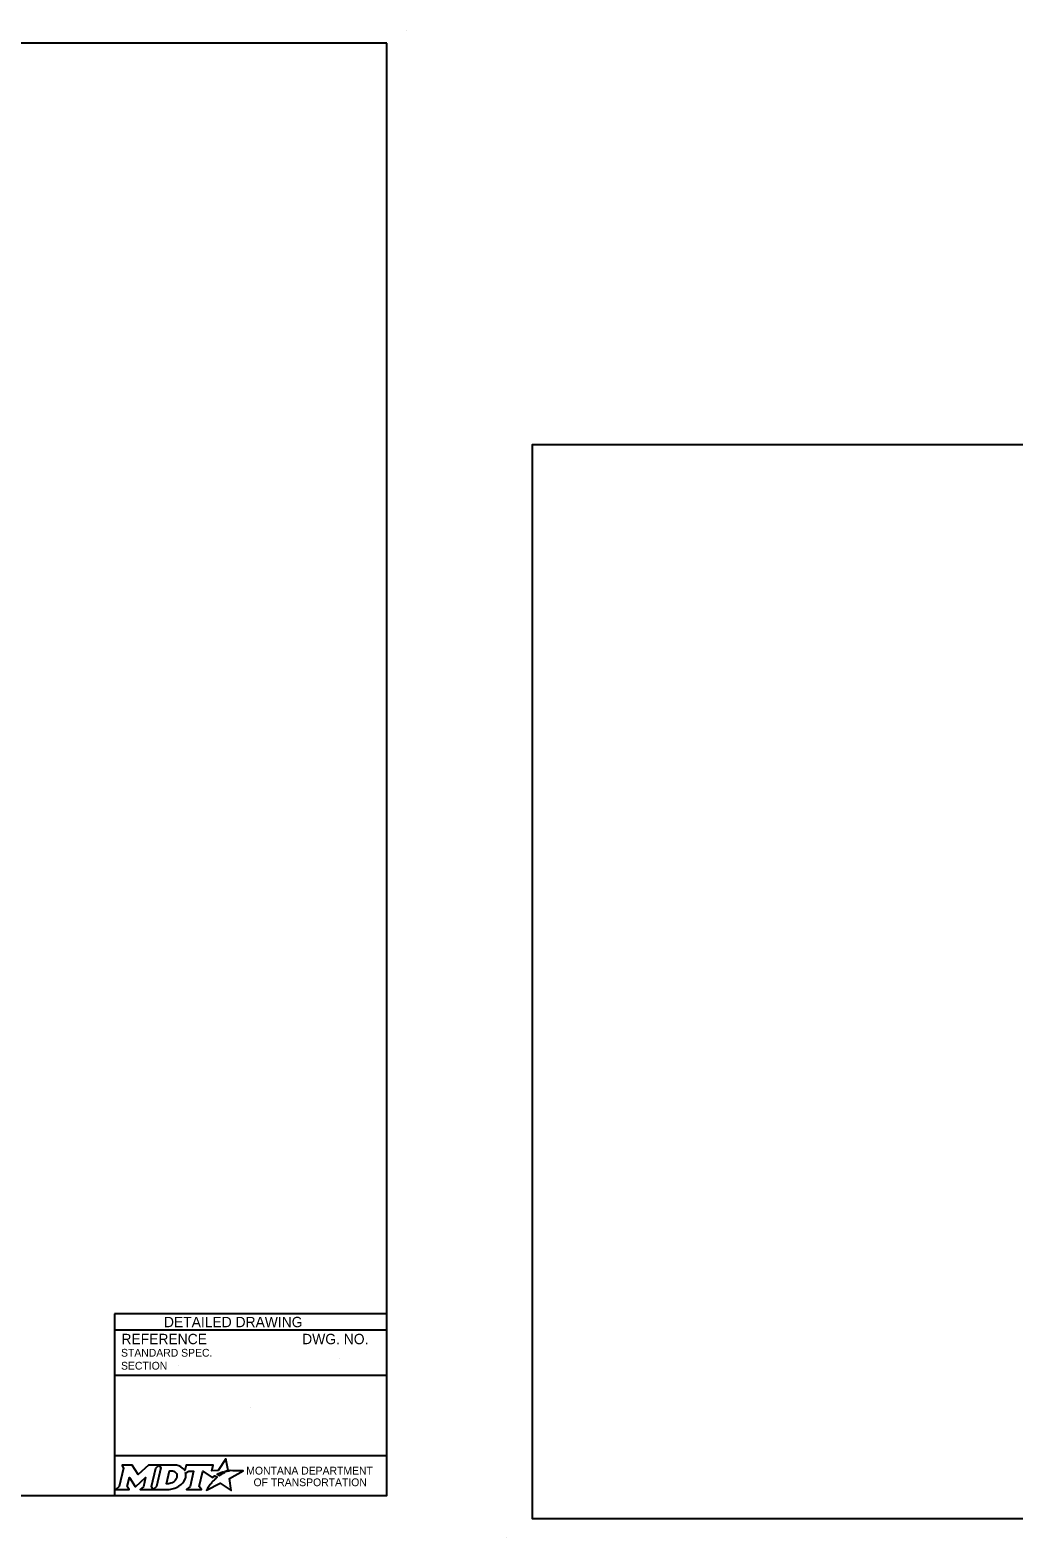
# Model space of a CAD drawing. Extents: x 49991.4 to 50021, y 49987.6 to 50011.4.
# Drawn here: x 50005.86 to 50013.45, y 49999.74 to 50011.36 of the extents above; entities that cross this region are included whole.
import ezdxf

# ---------------------------------------------------------------- set-up
doc = ezdxf.new("R2010")
doc.units = 0
doc.layers.add('Level 1', color=7, linetype='Continuous')
doc.layers.add('Level 2', color=7, linetype='Continuous')

msp = doc.modelspace()

# ---------------------------------------------------------------- linework, layer by layer
at = {"layer": 'Level 1'}
for p, q in [((50008.765, 50011.363), (50008.765, 50011.363)), ((50009.537, 49999.736), (50009.537, 49999.736))]:
    msp.add_line(p, q, dxfattribs=at)
for points in [[(50008.615, 50011.263), (50000.336, 50011.263), (50000.336, 50000.062), (50008.615, 50000.062)], [(50020.938, 50008.165), (50009.737, 50008.165), (50009.737, 49999.886), (50020.938, 49999.886)]]:
    msp.add_lwpolyline(points, close=True, dxfattribs=at)
at = {"layer": 'Level 2'}
for p, q in [((50008.615, 50001.462), (50006.515, 50001.462)), ((50006.515, 50001.462), (50006.515, 50000.062)), ((50008.615, 50001.337), (50006.515, 50001.337)), ((50007.009, 50001.063), (50007.009, 50001.063)), ((50008.251, 50001.122), (50008.251, 50001.122)), ((50008.615, 50000.987), (50006.515, 50000.987)), ((50007.565, 50000.738), (50007.565, 50000.738)), ((50008.615, 50000.369), (50006.515, 50000.369))]:
    msp.add_line(p, q, dxfattribs=at)
for points in [[(50007.377, 50000.245), (50007.367, 50000.25), (50007.378, 50000.253), (50007.39, 50000.255), (50007.373, 50000.345), (50007.313, 50000.254), (50007.266, 50000.253), (50007.276, 50000.297), (50007.067, 50000.297), (50007.057, 50000.255), (50007.051, 50000.263)], [(50006.57, 50000.297), (50006.584, 50000.274), (50006.551, 50000.131), (50006.525, 50000.108), (50006.627, 50000.108), (50006.613, 50000.131), (50006.629, 50000.201), (50006.673, 50000.132), (50006.678, 50000.132), (50006.753, 50000.202), (50006.737, 50000.13), (50006.712, 50000.108), (50006.814, 50000.108), (50006.8, 50000.132), (50006.833, 50000.274)], [(50006.833, 50000.274), (50006.859, 50000.297), (50006.776, 50000.297), (50006.697, 50000.224), (50006.652, 50000.297), (50006.57, 50000.297)], [(50006.972, 50000.297), (50006.859, 50000.297), (50006.873, 50000.275), (50006.839, 50000.131), (50006.814, 50000.108), (50006.925, 50000.108)], [(50006.996, 50000.211), (50006.995, 50000.203), (50006.992, 50000.193), (50006.988, 50000.185), (50006.982, 50000.178), (50006.976, 50000.171), (50006.968, 50000.164), (50006.959, 50000.16), (50006.95, 50000.156), (50006.941, 50000.154), (50006.932, 50000.153), (50006.916, 50000.153), (50006.94, 50000.253), (50006.956, 50000.253), (50006.963, 50000.252), (50006.971, 50000.25), (50006.977, 50000.247), (50006.983, 50000.243), (50006.988, 50000.238), (50006.992, 50000.232), (50006.995, 50000.226), (50006.996, 50000.218), (50006.996, 50000.215), (50006.996, 50000.211)], [(50007.064, 50000.238), (50007.088, 50000.251), (50007.125, 50000.251), (50007.097, 50000.131), (50007.069, 50000.108), (50007.185, 50000.108), (50007.168, 50000.131), (50007.196, 50000.251), (50007.268, 50000.2), (50007.289, 50000.215), (50007.309, 50000.204)], [(50007.253, 50000.148), (50007.237, 50000.124), (50007.233, 50000.116), (50007.227, 50000.107), (50007.225, 50000.103), (50007.33, 50000.156), (50007.414, 50000.101), (50007.401, 50000.194), (50007.508, 50000.252), (50007.458, 50000.253), (50007.428, 50000.253), (50007.407, 50000.254), (50007.401, 50000.252), (50007.396, 50000.251), (50007.387, 50000.249), (50007.377, 50000.245)], [(50007.327, 50000.217), (50007.324, 50000.215), (50007.306, 50000.225), (50007.316, 50000.231), (50007.32, 50000.233), (50007.329, 50000.237), (50007.335, 50000.239), (50007.343, 50000.243), (50007.35, 50000.245), (50007.362, 50000.238), (50007.358, 50000.236), (50007.353, 50000.233), (50007.349, 50000.231), (50007.344, 50000.228), (50007.342, 50000.227), (50007.339, 50000.225), (50007.337, 50000.224), (50007.334, 50000.222), (50007.332, 50000.221), (50007.329, 50000.219), (50007.327, 50000.217)], [(50006.97, 50000.116), (50006.979, 50000.118), (50006.992, 50000.124), (50007.012, 50000.135)], [(50007.267, 50000.164), (50007.267, 50000.164)]]:
    msp.add_lwpolyline(points, dxfattribs=at)
for centre, radius, start, end in [((50006.995, 50000.219), 0.0709, 339.5329, 15.8582), ((50006.951, 50000.236), 0.118, 300.9103, 339.1383)]:
    msp.add_arc(centre, radius, start, end, dxfattribs=at)
for centre, major_axis, ratio, start_param, end_param in [((50006.97, 50000.25), (0.0834, -0.0037), 0.568097, 0.61298, 1.570796), ((50007.026, 50000.257), (0.0361, -0.0295), 0.469099, 1.225588, 1.570796), ((50006.925, 50000.257), (0, 0.148), 0.987302, 3.139398, 3.456847), ((50007.26, 50000.156), (-0.00694, -0.00806), 0.008222, 0, 3.137361), ((50007.276, 50000.174), (-0.0098, -0.0102), 0.016458, 3.141593, 6.279097), ((50007.297, 50000.194), (-0.0112, -0.0097), 0.021651, 3.157348, 6.283185)]:
    msp.add_ellipse(centre, major_axis=major_axis, ratio=ratio, start_param=start_param, end_param=end_param, dxfattribs=at)

# ---------------------------------------------------------------- texts
for s, height, p in [('DETAILED DRAWING', 0.0799, (50006.896, 50001.36)), ('REFERENCE', 0.08, (50006.568, 50001.229)), ('DWG. NO.', 0.08, (50007.962, 50001.229)), ('STANDARD SPEC.', 0.06, (50006.565, 50001.133)), ('SECTION', 0.06, (50006.565, 50001.033)), ('MONTANA DEPARTMENT', 0.06, (50007.531, 50000.224)), ('OF TRANSPORTATION', 0.06, (50007.587, 50000.134))]:
    msp.add_text(s, height=height, dxfattribs=at).set_placement(p)

doc.saveas('drawing.dxf')
